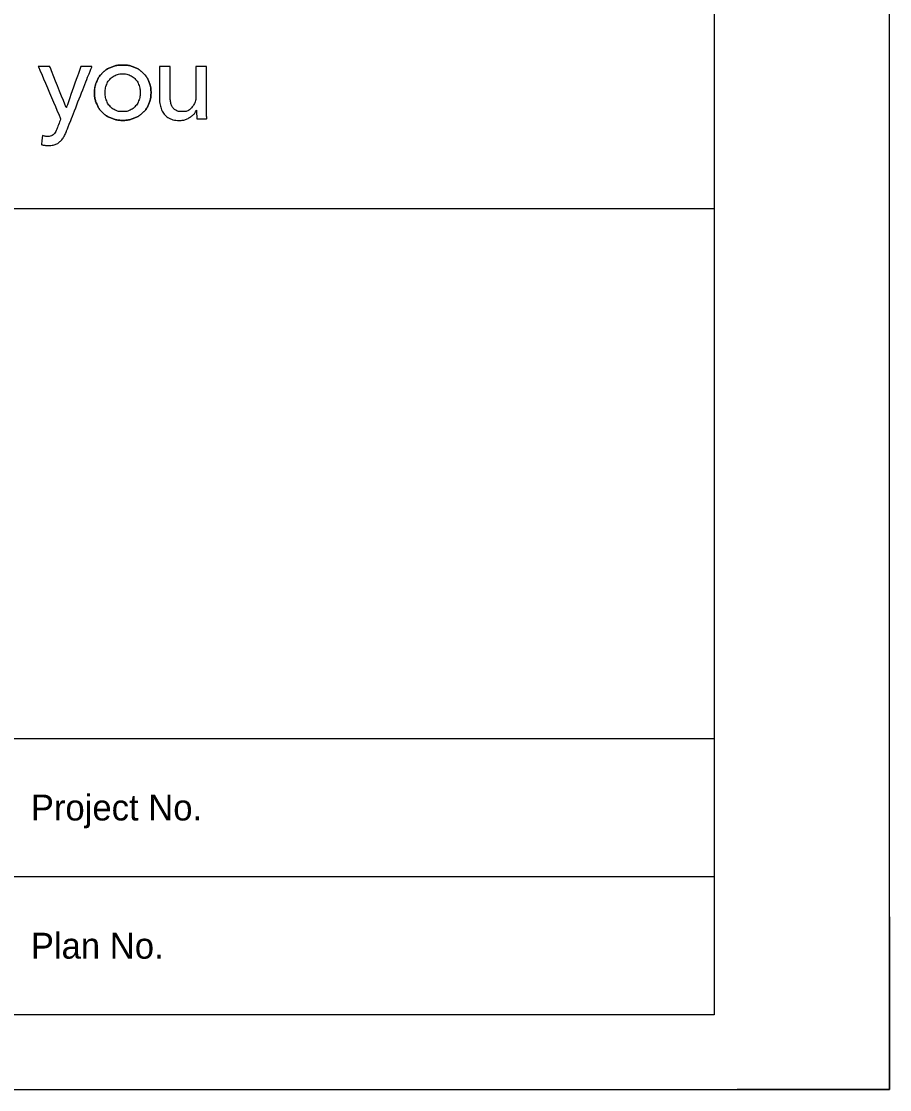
# Model space of a CAD drawing. Extents: x 613360 to 613780, y 4825621 to 4825911.
# Drawn here: x 613750.11 to 613780.27, y 4825620.91 to 4825658.01 of the extents above; entities that cross this region are included whole.
import ezdxf

# ---------------------------------------------------------------- set-up
doc = ezdxf.new("R2010")
doc.units = 0
for name, color, linetype in [('G-ANNO-TTLB-TEXT', 7, 'Continuous'), ('G-TTLB-LOGO', 7, 'Continuous'), ('G-TTLB-OTLN', 7, 'Continuous'), ('G-TTLB-OTLN-PB', 7, 'Continuous')]:
    doc.layers.add(name, color=color, linetype=linetype)

msp = doc.modelspace()

# ---------------------------------------------------------------- linework, layer by layer
at = {"layer": 'G-TTLB-LOGO'}
for points in [[(613751.669, 4825655.017), (613751.669, 4825655.017), (613751.677, 4825655.017), (613751.677, 4825655.017), (613751.677, 4825655.017), (613752.18, 4825656.446), (613752.18, 4825656.446), (613752.18, 4825656.446), (613752.564, 4825656.446), (613752.564, 4825656.446), (613752.564, 4825656.446), (613751.681, 4825654.195), (613751.681, 4825654.195), (613751.65, 4825654.119), (613751.617, 4825654.05), (613751.581, 4825653.99), (613751.545, 4825653.93), (613751.503, 4825653.879), (613751.454, 4825653.836), (613751.405, 4825653.794), (613751.348, 4825653.761), (613751.283, 4825653.738), (613751.218, 4825653.715), (613751.141, 4825653.704), (613751.051, 4825653.704), (613751.012, 4825653.704), (613750.973, 4825653.706), (613750.934, 4825653.71), (613750.894, 4825653.713), (613750.854, 4825653.72), (613750.813, 4825653.731), (613750.813, 4825653.731), (613750.847, 4825654.049), (613750.847, 4825654.049), (613750.909, 4825654.029), (613750.969, 4825654.019), (613751.028, 4825654.019), (613751.123, 4825654.019), (613751.193, 4825654.045), (613751.239, 4825654.097), (613751.285, 4825654.15), (613751.327, 4825654.225), (613751.366, 4825654.322), (613751.366, 4825654.322), (613751.481, 4825654.626), (613751.481, 4825654.626), (613751.481, 4825654.626), (613750.701, 4825656.446), (613750.701, 4825656.446), (613750.701, 4825656.446), (613751.105, 4825656.446), (613751.105, 4825656.446), (613751.105, 4825656.446), (613751.669, 4825655.017), (613751.669, 4825655.017)], [(613751.669, 4825655.017), (613751.669, 4825655.017), (613751.677, 4825655.017), (613751.677, 4825655.017), (613751.677, 4825655.017), (613752.18, 4825656.446), (613752.18, 4825656.446), (613752.18, 4825656.446), (613752.564, 4825656.446), (613752.564, 4825656.446), (613752.564, 4825656.446), (613751.681, 4825654.195), (613751.681, 4825654.195), (613751.65, 4825654.119), (613751.617, 4825654.05), (613751.581, 4825653.99), (613751.545, 4825653.93), (613751.503, 4825653.879), (613751.454, 4825653.836), (613751.405, 4825653.794), (613751.348, 4825653.761), (613751.283, 4825653.738), (613751.218, 4825653.715), (613751.141, 4825653.704), (613751.051, 4825653.704), (613751.012, 4825653.704), (613750.973, 4825653.706), (613750.934, 4825653.71), (613750.894, 4825653.713), (613750.854, 4825653.72), (613750.813, 4825653.731), (613750.813, 4825653.731), (613750.847, 4825654.049), (613750.847, 4825654.049), (613750.909, 4825654.029), (613750.969, 4825654.019), (613751.028, 4825654.019), (613751.123, 4825654.019), (613751.193, 4825654.045), (613751.239, 4825654.097), (613751.285, 4825654.15), (613751.327, 4825654.225), (613751.366, 4825654.322), (613751.366, 4825654.322), (613751.481, 4825654.626), (613751.481, 4825654.626), (613751.481, 4825654.626), (613750.701, 4825656.446), (613750.701, 4825656.446), (613750.701, 4825656.446), (613751.105, 4825656.446), (613751.105, 4825656.446), (613751.105, 4825656.446), (613751.669, 4825655.017), (613751.669, 4825655.017)], [(613754.618, 4825655.54), (613754.618, 4825655.399), (613754.593, 4825655.269), (613754.543, 4825655.152), (613754.493, 4825655.034), (613754.424, 4825654.932), (613754.335, 4825654.846), (613754.248, 4825654.761), (613754.143, 4825654.694), (613754.023, 4825654.647), (613753.902, 4825654.599), (613753.773, 4825654.576), (613753.635, 4825654.576), (613753.497, 4825654.576), (613753.367, 4825654.599), (613753.247, 4825654.647), (613753.126, 4825654.694), (613753.023, 4825654.761), (613752.936, 4825654.846), (613752.849, 4825654.932), (613752.78, 4825655.034), (613752.73, 4825655.152), (613752.68, 4825655.269), (613752.655, 4825655.399), (613752.655, 4825655.54), (613752.655, 4825655.681), (613752.68, 4825655.809), (613752.73, 4825655.926), (613752.78, 4825656.042), (613752.849, 4825656.143), (613752.936, 4825656.227), (613753.023, 4825656.312), (613753.126, 4825656.378), (613753.247, 4825656.425), (613753.367, 4825656.472), (613753.497, 4825656.496), (613753.635, 4825656.496), (613753.773, 4825656.496), (613753.902, 4825656.472), (613754.023, 4825656.425), (613754.143, 4825656.378), (613754.248, 4825656.312), (613754.335, 4825656.227), (613754.424, 4825656.143), (613754.493, 4825656.042), (613754.543, 4825655.926), (613754.593, 4825655.809), (613754.618, 4825655.681), (613754.618, 4825655.54)], [(613752.678, 4825655.76), (613752.69, 4825655.818), (613752.708, 4825655.873), (613752.73, 4825655.926), (613752.78, 4825656.042), (613752.849, 4825656.143), (613752.936, 4825656.227), (613753.023, 4825656.312), (613753.126, 4825656.378), (613753.247, 4825656.425), (613753.367, 4825656.472), (613753.497, 4825656.496), (613753.635, 4825656.496), (613753.773, 4825656.496), (613753.902, 4825656.472), (613754.023, 4825656.425), (613754.143, 4825656.378), (613754.248, 4825656.312), (613754.335, 4825656.227), (613754.424, 4825656.143), (613754.493, 4825656.042), (613754.543, 4825655.926), (613754.593, 4825655.809), (613754.618, 4825655.681), (613754.618, 4825655.54)], [(613756.214, 4825654.626), (613756.208, 4825654.672), (613756.205, 4825654.724), (613756.202, 4825654.781), (613756.2, 4825654.839), (613756.198, 4825654.887), (613756.198, 4825654.925), (613756.198, 4825654.925), (613756.191, 4825654.925), (613756.191, 4825654.925), (613756.144, 4825654.828), (613756.067, 4825654.745), (613755.958, 4825654.677), (613755.849, 4825654.61), (613755.728, 4825654.576), (613755.595, 4825654.576), (613755.477, 4825654.576), (613755.376, 4825654.595), (613755.29, 4825654.633), (613755.204, 4825654.672), (613755.133, 4825654.725), (613755.079, 4825654.793), (613755.024, 4825654.861), (613754.982, 4825654.939), (613754.956, 4825655.029), (613754.929, 4825655.118), (613754.915, 4825655.214), (613754.915, 4825655.317), (613754.915, 4825655.317), (613754.915, 4825656.446), (613754.915, 4825656.446), (613754.915, 4825656.446), (613755.277, 4825656.446), (613755.277, 4825656.446), (613755.277, 4825656.446), (613755.277, 4825655.44), (613755.277, 4825655.44), (613755.277, 4825655.365), (613755.282, 4825655.295), (613755.294, 4825655.227), (613755.305, 4825655.159), (613755.326, 4825655.099), (613755.357, 4825655.048), (613755.388, 4825654.997), (613755.43, 4825654.956), (613755.484, 4825654.925), (613755.538, 4825654.895), (613755.607, 4825654.879), (613755.691, 4825654.879), (613755.837, 4825654.879), (613755.955, 4825654.933), (613756.044, 4825655.042), (613756.134, 4825655.151), (613756.179, 4825655.296), (613756.179, 4825655.478), (613756.179, 4825655.478), (613756.179, 4825656.446), (613756.179, 4825656.446), (613756.179, 4825656.446), (613756.54, 4825656.446), (613756.54, 4825656.446), (613756.54, 4825656.446), (613756.54, 4825655.017), (613756.54, 4825655.017), (613756.54, 4825654.969), (613756.542, 4825654.906), (613756.544, 4825654.829), (613756.546, 4825654.752), (613756.55, 4825654.684), (613756.556, 4825654.626), (613756.556, 4825654.626), (613756.214, 4825654.626), (613756.214, 4825654.626)], [(613756.214, 4825654.626), (613756.208, 4825654.672), (613756.205, 4825654.724), (613756.202, 4825654.781), (613756.2, 4825654.839), (613756.198, 4825654.887), (613756.198, 4825654.925), (613756.198, 4825654.925), (613756.191, 4825654.925), (613756.191, 4825654.925), (613756.144, 4825654.828), (613756.067, 4825654.745), (613755.958, 4825654.677), (613755.849, 4825654.61), (613755.728, 4825654.576), (613755.595, 4825654.576), (613755.477, 4825654.576), (613755.376, 4825654.595), (613755.29, 4825654.633), (613755.204, 4825654.672), (613755.133, 4825654.725), (613755.079, 4825654.793), (613755.024, 4825654.861), (613754.982, 4825654.939), (613754.956, 4825655.029), (613754.929, 4825655.118), (613754.915, 4825655.214), (613754.915, 4825655.317), (613754.915, 4825655.317), (613754.915, 4825656.446), (613754.915, 4825656.446), (613754.915, 4825656.446), (613755.277, 4825656.446), (613755.277, 4825656.446), (613755.277, 4825656.446), (613755.277, 4825655.44), (613755.277, 4825655.44), (613755.277, 4825655.365), (613755.282, 4825655.295), (613755.294, 4825655.227), (613755.305, 4825655.159), (613755.326, 4825655.099), (613755.357, 4825655.048), (613755.388, 4825654.997), (613755.43, 4825654.956), (613755.484, 4825654.925), (613755.538, 4825654.895), (613755.607, 4825654.879), (613755.691, 4825654.879), (613755.837, 4825654.879), (613755.955, 4825654.933), (613756.044, 4825655.042), (613756.134, 4825655.151), (613756.179, 4825655.296), (613756.179, 4825655.478), (613756.179, 4825655.478), (613756.179, 4825656.446), (613756.179, 4825656.446), (613756.179, 4825656.446), (613756.54, 4825656.446), (613756.54, 4825656.446), (613756.54, 4825656.446), (613756.54, 4825655.017), (613756.54, 4825655.017), (613756.54, 4825654.969), (613756.542, 4825654.906), (613756.544, 4825654.829), (613756.546, 4825654.752), (613756.55, 4825654.684), (613756.556, 4825654.626), (613756.556, 4825654.626), (613756.214, 4825654.626), (613756.214, 4825654.626)], [(613754.242, 4825655.538), (613754.242, 4825655.624), (613754.228, 4825655.707), (613754.201, 4825655.787), (613754.174, 4825655.866), (613754.135, 4825655.935), (613754.084, 4825655.995), (613754.032, 4825656.056), (613753.969, 4825656.103), (613753.893, 4825656.139), (613753.817, 4825656.175), (613753.731, 4825656.193), (613753.633, 4825656.193), (613753.535, 4825656.193), (613753.448, 4825656.175), (613753.373, 4825656.139), (613753.297, 4825656.103), (613753.233, 4825656.056), (613753.182, 4825655.995), (613753.131, 4825655.935), (613753.091, 4825655.866), (613753.065, 4825655.787), (613753.037, 4825655.707), (613753.024, 4825655.624), (613753.024, 4825655.538), (613753.024, 4825655.451), (613753.037, 4825655.368), (613753.065, 4825655.289), (613753.091, 4825655.21), (613753.131, 4825655.139), (613753.182, 4825655.078), (613753.233, 4825655.017), (613753.297, 4825654.968), (613753.373, 4825654.933), (613753.448, 4825654.897), (613753.535, 4825654.879), (613753.633, 4825654.879), (613753.731, 4825654.879), (613753.817, 4825654.897), (613753.893, 4825654.933), (613753.969, 4825654.968), (613754.032, 4825655.017), (613754.084, 4825655.078), (613754.135, 4825655.139), (613754.174, 4825655.21), (613754.201, 4825655.289), (613754.228, 4825655.368), (613754.242, 4825655.451), (613754.242, 4825655.538)], [(613754.242, 4825655.538), (613754.242, 4825655.624), (613754.228, 4825655.707), (613754.201, 4825655.787), (613754.174, 4825655.866), (613754.135, 4825655.935), (613754.084, 4825655.995), (613754.032, 4825656.056), (613753.969, 4825656.103), (613753.893, 4825656.139), (613753.817, 4825656.175), (613753.731, 4825656.193), (613753.633, 4825656.193), (613753.535, 4825656.193), (613753.448, 4825656.175), (613753.373, 4825656.139), (613753.297, 4825656.103), (613753.233, 4825656.056), (613753.182, 4825655.995), (613753.131, 4825655.935), (613753.091, 4825655.866), (613753.065, 4825655.787), (613753.037, 4825655.707), (613753.024, 4825655.624), (613753.024, 4825655.538), (613753.024, 4825655.451), (613753.037, 4825655.368), (613753.065, 4825655.289), (613753.091, 4825655.21), (613753.131, 4825655.139), (613753.182, 4825655.078), (613753.233, 4825655.017), (613753.297, 4825654.968), (613753.373, 4825654.933), (613753.448, 4825654.897), (613753.535, 4825654.879), (613753.633, 4825654.879), (613753.731, 4825654.879), (613753.817, 4825654.897), (613753.893, 4825654.933), (613753.969, 4825654.968), (613754.032, 4825655.017), (613754.084, 4825655.078), (613754.135, 4825655.139), (613754.174, 4825655.21), (613754.201, 4825655.289), (613754.228, 4825655.368), (613754.242, 4825655.451), (613754.242, 4825655.538)], [(613754.618, 4825655.54), (613754.618, 4825655.399), (613754.593, 4825655.269), (613754.543, 4825655.152), (613754.493, 4825655.034), (613754.424, 4825654.932), (613754.335, 4825654.846), (613754.248, 4825654.761), (613754.143, 4825654.694), (613754.023, 4825654.647), (613753.902, 4825654.599), (613753.773, 4825654.576), (613753.635, 4825654.576), (613753.497, 4825654.576), (613753.367, 4825654.599), (613753.247, 4825654.647), (613753.126, 4825654.694), (613753.023, 4825654.761), (613752.936, 4825654.846), (613752.849, 4825654.932), (613752.78, 4825655.034), (613752.73, 4825655.152), (613752.68, 4825655.269), (613752.655, 4825655.399), (613752.655, 4825655.54), (613752.655, 4825655.617), (613752.663, 4825655.69), (613752.678, 4825655.76)]]:
    msp.add_open_spline(points, degree=3, dxfattribs=at)
at = {"layer": 'G-TTLB-OTLN'}
for p, q in [((613774.178, 4825651.507), (613710.777, 4825651.507)), ((613380.086, 4825633.107), (613774.178, 4825633.107)), ((613749.425, 4825628.307), (613774.178, 4825628.307))]:
    msp.add_line(p, q, dxfattribs=at)
msp.add_lwpolyline([(613380.085, 4825892.077), (613774.178, 4825892.077), (613774.178, 4825623.508), (613380.085, 4825623.508)], close=True, dxfattribs=at)
at = {"layer": 'G-TTLB-OTLN-PB'}
for p, q in [((613780.27, 4825626.91), (613780.27, 4825620.908)), ((613780.27, 4825620.908), (613774.978, 4825620.908))]:
    msp.add_line(p, q, dxfattribs=at)
msp.add_lwpolyline([(613359.578, 4825620.908), (613780.27, 4825620.908), (613780.27, 4825894.677), (613359.578, 4825894.677)], close=True, dxfattribs=at)

# ---------------------------------------------------------------- texts
at = {"layer": 'G-ANNO-TTLB-TEXT'}
for s, p in [('Project No.', (613750.441, 4825630.257)), ('Plan No.', (613750.441, 4825625.457))]:
    msp.add_text(s, height=0.9, dxfattribs=at).set_placement(p)

doc.saveas('drawing.dxf')
